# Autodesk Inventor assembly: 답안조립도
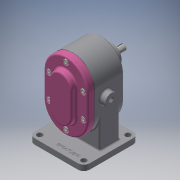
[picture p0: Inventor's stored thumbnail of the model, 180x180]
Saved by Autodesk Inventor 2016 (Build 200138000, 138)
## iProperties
Created: 2020-09
Part Number: 답안조립도
Material: 일반
Document SubType Name: Assembly
Designer: Windows7
Author: Windows7
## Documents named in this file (11)
- C:\Users\Windows7\Documents\700906V1038\답안조립도.iam
- C:\Users\Windows7\Documents\700906V1038\본체.ipt
- C:\Users\Windows7\Documents\700906V1038\부품+문제도면\700906V1038\개스킷.ipt
- C:\Users\Windows7\Documents\700906V1038\부품+문제도면\700906V1038\메인축.ipt
- C:\Users\Windows7\Documents\700906V1038\부품+문제도면\700906V1038\베어링부시.ipt
- C:\Users\Windows7\Documents\700906V1038\부품+문제도면\700906V1038\볼트 M5.ipt
- C:\Users\Windows7\Documents\700906V1038\부품+문제도면\700906V1038\서브축.ipt
- C:\Users\Windows7\Documents\700906V1038\부품+문제도면\700906V1038\스퍼기어.ipt
- C:\Users\Windows7\Documents\700906V1038\부품+문제도면\700906V1038\오일 실 16 28 7.ipt
- C:\Users\Windows7\Documents\700906V1038\부품+문제도면\700906V1038\커버.ipt
- C:\Users\Windows7\Documents\700906V1038\부품+문제도면\700906V1038\키 6 x 6 x 18.ipt
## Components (1 placed, 1 different names)
1. 개스킷:1
